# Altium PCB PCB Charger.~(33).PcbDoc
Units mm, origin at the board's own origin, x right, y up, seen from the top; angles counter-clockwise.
Board outline 70.24 x 66.94 mm, 2 copper layers (Top Layer, Bottom Layer), stack 1.57 mm thick; 23 components, 11 nets, 111 pads, 0 vias.
Unrouted connection lines stored in the file: 19.
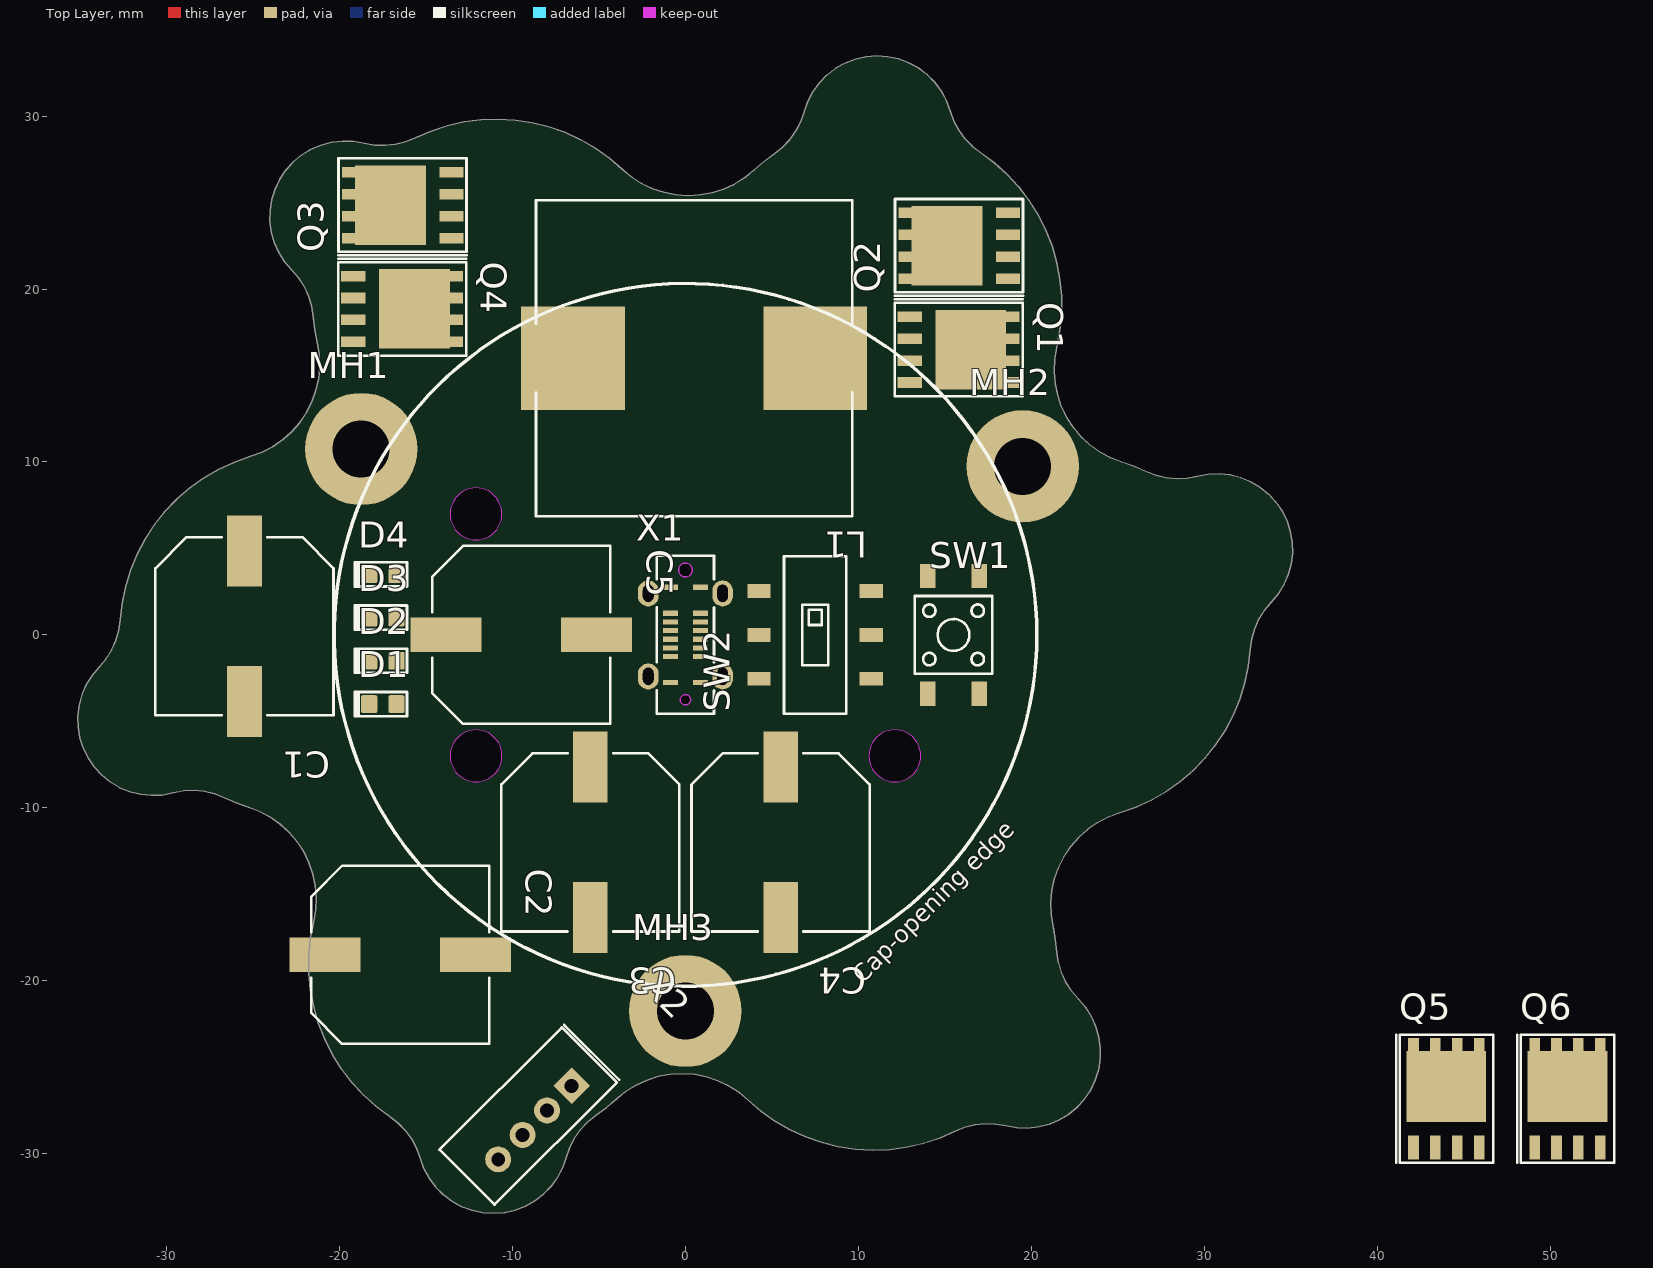
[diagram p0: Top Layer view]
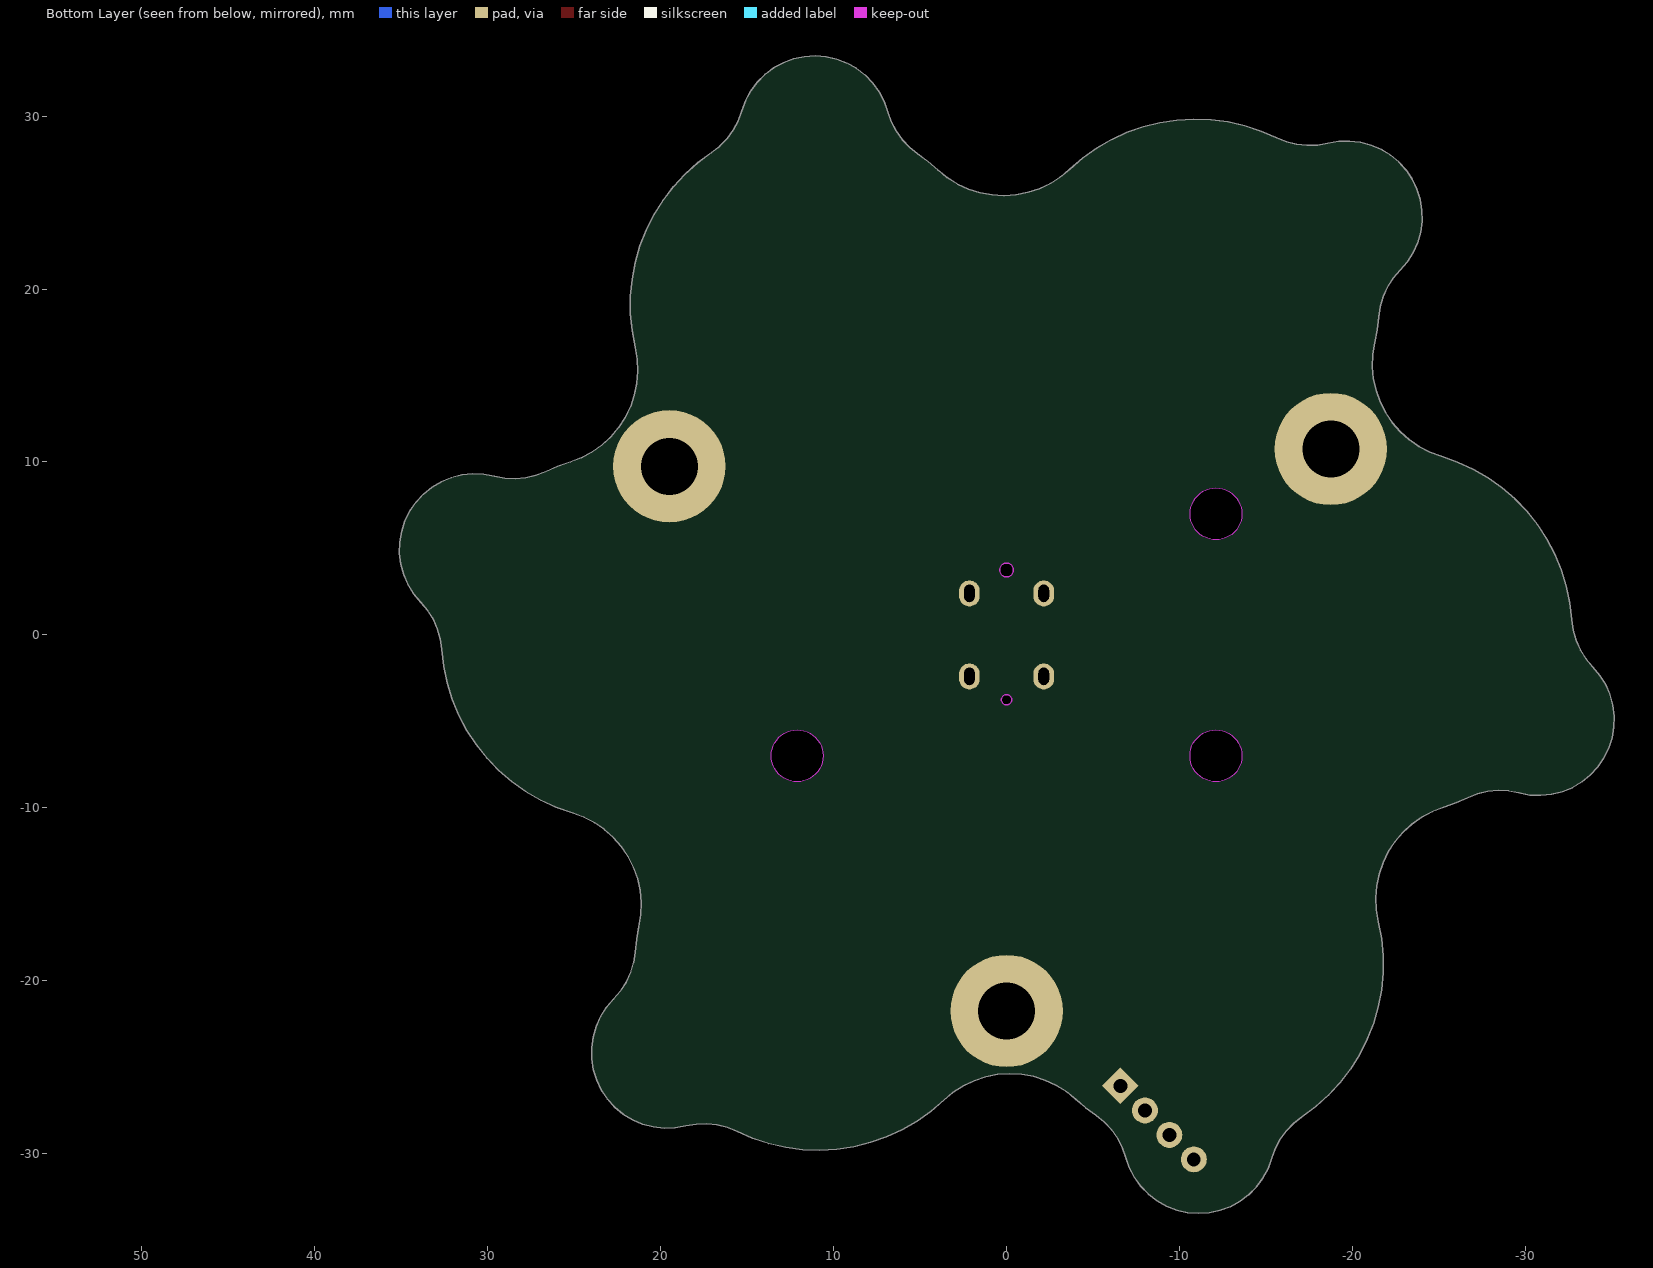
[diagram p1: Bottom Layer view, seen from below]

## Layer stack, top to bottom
Top Solder: solder mask 0.0102, Solder Resist, Dk 3.5
Top Layer: signal copper 0.0356
Dielectric 1: core 1.4986, Core-043, Dk 4.3
Bottom Layer: signal copper 0.0356
Bottom Solder: solder mask 0.0102, Solder Resist, Dk 3.5

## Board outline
331 vertices, not listed, extent -35.137,-33.454 35.107,33.486
cut-out: 10.61,-6.994 ccw(c12.11,-6.994) 12.11,-8.494 ccw(c12.11,-6.994) 13.61,-6.994 ccw(c12.11,-6.994) 12.11,-5.494 ccw(c12.11,-6.994)
cut-out: -13.61,6.994 ccw(c-12.11,6.994) -12.11,5.494 ccw(c-12.11,6.994) -10.61,6.994 ccw(c-12.11,6.994) -12.11,8.494 ccw(c-12.11,6.994)
cut-out: -13.609,-6.996 ccw(c-12.109,-6.996) -12.109,-8.496 ccw(c-12.109,-6.996) -10.609,-6.996 ccw(c-12.109,-6.996) -12.109,-5.496 ccw(c-12.109,-6.996)

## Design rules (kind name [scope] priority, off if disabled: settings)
Clearance [All] p1: gap=0.254 ignorepadtopadclearanceinfootprint=FALSE
PolygonConnect [All] p1: connectstyle=Relief reliefconductorwidth=0.254 reliefentries=4 polygonreliefangle="90 Angle" airgapwidth=0.254
RoutingVias [All] p1: holewidth=0.711 width=1.27 viastyle="Through Hole" minholewidth=0.711 minwidth=1.27 maxholewidth=0.711 maxwidth=1.27
SolderMaskExpansion [All] p1: expansion=0.102 istentingtop=FALSE
SupplyNets "Schematic Supply Nets_1" [InNet('3V3')] p1: voltage=0.000
SupplyNets "Schematic Supply Nets" [InNet('GND')] p2: voltage=0.000
Width [All] p1: maxlimit=0.254 minlimit=0.254 preferedwidth=0.254
30 further rules are at their usual default settings.

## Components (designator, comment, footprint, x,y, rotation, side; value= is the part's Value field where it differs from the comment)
C1 "EEHZA1J560P" CAP_SMD_10X10.2 -25.5,0.5 r270 top
C2 "EEHZA1J560P" CAP_SMD_10X10.2 -16.5,-18.5 r0 top
C3 "EEHZA1J560P" CAP_SMD_10X10.2 -5.5,-12 r270 top
C4 "EEHZA1J560P" CAP_SMD_10X10.2 5.5,-12 r270 top
C5 "EEHZA1J560P" CAP_SMD_10X10.2 -9.5,0 r0 top
D1 "XL-1608SURC-06" DIODE_0603 -17.5,-4 r0 top
D2 "XL-1608SURC-06" DIODE_0603 -17.5,-1.5 r0 top
D3 "XL-1608SURC-06" DIODE_0603 -17.5,1 r0 top
D4 "XL-1608SURC-06" DIODE_0603 -17.5,3.5 r0 top
L1 "MTF1810-150M" MTF1810-150M 0.5,16 r180 top
MH1 "M?" "M3 Plated" -18.75,10.75 r0 top locked
MH2 "M?" "M3 Plated" 19.5,9.75 r0 top locked
MH3 "M?" "M3 Plated" 0,-21.75 r0 top locked
Q1 "CRSM038N10N4" "DFN-8 (5x6)" 16.5,16.5 r270 top
Q2 "CRSM038N10N4" "DFN-8 (5x6)" 15.118,22.506 r90 top
Q3 "CRSM038N10N4" "DFN-8 (5x6)" -17.061,24.854 r90 top
Q4 "CRSM038N10N4" "DFN-8 (5x6)" -15.678,18.847 r270 top
Q5 "E060N2P3HL1" "DFN-8 (5x6)" 44.006,-26.118 r0 top
Q6 "E060N2P3HL1" "DFN-8 (5x6)" 51.006,-26.118 r0 top
SW1 "TS4560TP" TS4560TP 15.5,0 r90 top
SW2 "SS-3235S-L3" SS-3235S-L3 7.5,0 r90 top
X1 "TYPE-C 16P LTH6.8" "TYPE-C 16P LTH6.8" 0,0 r90 top
X2 "B4B-PH-K-S(LF)(SN)" B4B-PH-K-S(LF)(SN) -8.707,-28.207 r45 top

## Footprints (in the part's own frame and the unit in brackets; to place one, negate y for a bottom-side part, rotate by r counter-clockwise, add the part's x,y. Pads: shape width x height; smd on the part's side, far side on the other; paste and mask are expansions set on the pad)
B4B-PH-K-S(LF)(SN) [mm] "JST PH 2.00mm 1x4 THT Vertical"
  rect 1.5x1.5 hole 0.8: 1(3,0)
  round 1.5 hole 0.8: 2(1,0) 3(-1,0) 4(-3,0)
  silkscreen extent -5,-1.7 5.2,2.8, body extent -4.95,-1.7 4.95,2.8, height 6.01
CAP_SMD_10X10.2 [mm] "Elko, radial SMD FI10xH10.2mm"
  rect 4.1x2 smd: +(-4.35,0) -(4.35,0)
  silkscreen extent -5.15,-5.15 5.15,5.15, body extent -5.85,-5.15 5.85,5.15, height 10.21
"DFN-8 (5x6)" [mil] "Mosfet SMD footprint"
  rect 24x55 smd paste-3937.01 mask+2: D(-75,83) D(-25,83) D(25,83) D(75,83) G(75,-139) S(-75,-139) S(-25,-139) S(25,-139)
  rect 181.1x161.42 smd paste-3937.01 mask+2: D(0,0)
  silkscreen extent -114,-173 106,118, body extent -101,-150 101,93, height 42
DIODE_0603 [mm] "RES 0603"
  rrect20% 0.94x1.02 smd: A(0.79,0) K(-0.79,0)
  silkscreen extent -1.63,-0.7 1.4,0.7, body extent -0.8,-0.4 0.8,0.4, height 0.46
"M3 Plated" [mm] "M3 hole"
  round 6.5 hole 3.3: 1(0,0)
MTF1810-150M [mm] "Inductor SMD 18.2x18.2x8.9 mm"
  rect 6x6 smd: 1(-7,0) 2(7,0)
  silkscreen extent -9.14,-9.14 9.14,9.14, body extent -9.2,-9.11 9.1,9.11, height 9.02
SS-3235S-L3 [mm] "Slide switch"
  rect 0.8x1.35 smd: 1(-2.54,3.25) 1(-2.54,-3.25) 2(0,3.25) 2(0,-3.25) 3(2.54,3.25) 3(2.54,-3.25)
  silkscreen extent -4.55,-1.8 4.55,1.8, body extent -4.6,-3.45 4.5,3.45, height 7.56
TS4560TP [mm] "Switch tactile 4.5x4.5mm 6mmH"
  rect 1.4x0.9 smd: 1(-3.4,1.5) 2(3.4,1.5) 3(-3.4,-1.5) 4(3.4,-1.5)
  silkscreen extent -2.25,-2.25 2.25,2.25, body extent -3.25,-2.25 3.25,2.25, height 7.51
"TYPE-C 16P LTH6.8" [mm] "USB C 16P SMD Vertical 6.8mmH"
  rect 0.3x0.87 smd mask+0.051: A1(-2.75,0.865) A4(-1.25,0.865) A5(-0.75,0.865) A6(-0.25,0.865) A7(0.25,0.865) A8(0.75,0.865) A9(1.25,0.865) A12(2.75,0.865) B1(2.75,-0.865) B4(1.25,-0.865) B5(0.75,-0.865) B6(0.25,-0.865) B7(-0.25,-0.865) B8(-0.75,-0.865) B9(-1.25,-0.865) B12(-2.75,-0.865)
  oval 1.5x1.2 hole 0.61 slot 1 at 0 deg: CASE(-2.4,-2.15) CASE(-2.4,2.15) CASE(2.4,-2.15)
  oval 1.5x1.2 hole 0.61 slot 1 at 0 deg copper offset 0,0: CASE(2.4,2.15)
  Keep-Out Layer board cut-out: -3.45,0 -3.48,-0.13 -3.563,-0.234 -3.683,-0.292 -3.817,-0.292 -3.937,-0.234 -4.02,-0.13 -4.05,0 -4.05,0 -4.02,0.13 -3.937,0.235 -3.817,0.293 -3.683,0.293 -3.563,0.235 -3.48,0.13 -3.45,0
  Keep-Out Layer board cut-out: 4.15,0 4.111,-0.174 4,-0.313 3.839,-0.39 3.661,-0.39 3.501,-0.313 3.39,-0.174 3.35,0 3.35,0 3.39,0.174 3.501,0.313 3.661,0.39 3.839,0.39 4,0.313 4.111,0.174 4.15,0
  Keep-Out Layer circle w0.025: c-3.75,0 r0.3
  Keep-Out Layer circle w0.025: c3.75,0 r0.4
  Keep-Out Layer region: -3.45,0 -3.48,-0.13 -3.563,-0.234 -3.683,-0.292 -3.817,-0.292 -3.937,-0.234 -4.02,-0.13 -4.05,0 -4.05,0 -4.02,0.13 -3.937,0.235 -3.817,0.293 -3.683,0.293 -3.563,0.235 -3.48,0.13 -3.45,0
  Keep-Out Layer region: 4.15,0 4.111,-0.174 4,-0.313 3.839,-0.39 3.661,-0.39 3.501,-0.313 3.39,-0.174 3.35,0 3.35,0 3.39,0.174 3.501,0.313 3.661,0.39 3.839,0.39 4,0.313 4.111,0.174 4.15,0
  silkscreen extent -4.57,-1.65 4.57,1.65, body extent -4.47,-2.3 4.47,2.3, height 6.51

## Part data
C1 C2 C3 C4 C5: "Cap AL-EL 56uF 63V 30mR 1.8Ar SMD 10x10.2mm", Capacitance=56u, Manufacturer=Panasonic, Supplier Part Number 1=?, Voltage Rating=63V
D1 D2 D3 D4: "LED Red 0603 25mA", Manufacturer=Xinglight
L1: "Inductor 15uH 22Asat 10mR SMD 18x18x9 mm", Inductance=15uH, Manufacturer=COILMX, Resistance=10mR, Saturation current=22Asat, Supplier Part Number 1=?
MH1 MH2 MH3: library part "Mounting hole", "Generic mounting hole symbol"
Q1 Q2 Q3 Q4: "Nmos 100V 100A 3.6mR DFN-8(5x6)", Manufacturer=CRMICRO, Voltage=100V
Q5 Q6: "Nmos 60V 180A 2.3mR PDFN5x6-8", Manufacturer=Existar, Voltage=60V
SW1: "Switch Tactile SMD 4.5x4.5mm 6mmH SPST", Manufacturer="Shou Han"
SW2: "Switch Slide SMD 9.1x3.5mm 6.6mmH", Manufacturer="XKB Connection"
X1: "USB-C 16P SMD Vertical 6.50mmH", Manufacturer="Shou Han"
X2: "Pin header 1x4 2.00mmP THT Vertical JST PH", Manufacturer=JST

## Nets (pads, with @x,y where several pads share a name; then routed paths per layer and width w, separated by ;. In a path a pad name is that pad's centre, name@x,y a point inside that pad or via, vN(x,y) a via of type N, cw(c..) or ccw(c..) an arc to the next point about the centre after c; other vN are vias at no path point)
3V3: X2.1
GND: MH2.1 X1.A1 X1.A12 X1.B1 X1.B12 X1.CASE X2.2
NetQ5_D: Q5.D X1.A4 X1.A9 X1.B4 X1.B9
NetQ5_G: Q5.G Q6.G
NetQ5_S: Q5.S Q6.S
NetQ6_D: Q6.D
NetX1_A5: X1.A5
NetX1_B5: X1.B5
NetX2_3: X2.3
NetX2_4: X2.4
PACK+: MH1.1
pads on no net: C1.+ C1.- C2.+ C2.- C3.+ C3.- C4.+ C4.- C5.+ C5.- D1.A D1.K D2.A D2.K D3.A D3.K D4.A D4.K L1.1 L1.2 MH3.1 Q1.D Q1.G Q1.S Q2.D Q2.G Q2.S Q3.D Q3.G Q3.S Q4.D Q4.G Q4.S SW1.1 SW1.2 SW1.3 SW1.4 SW2.1 SW2.2 SW2.3 X1.A6 X1.A7 X1.A8 X1.B6 X1.B7 X1.B8

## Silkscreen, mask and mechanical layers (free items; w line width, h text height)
Top Overlay:
  circle w0.2: c0,0 r20.32
  text "Cap-opening edge" at 10.257,-20.214 h1 r45
Board:
  drawing of 334 lines, arcs and shapes, not listed
Dimensions:
  circle w0.1: c0,0 r13.985
  circle w0.1: c0,0 r22.225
